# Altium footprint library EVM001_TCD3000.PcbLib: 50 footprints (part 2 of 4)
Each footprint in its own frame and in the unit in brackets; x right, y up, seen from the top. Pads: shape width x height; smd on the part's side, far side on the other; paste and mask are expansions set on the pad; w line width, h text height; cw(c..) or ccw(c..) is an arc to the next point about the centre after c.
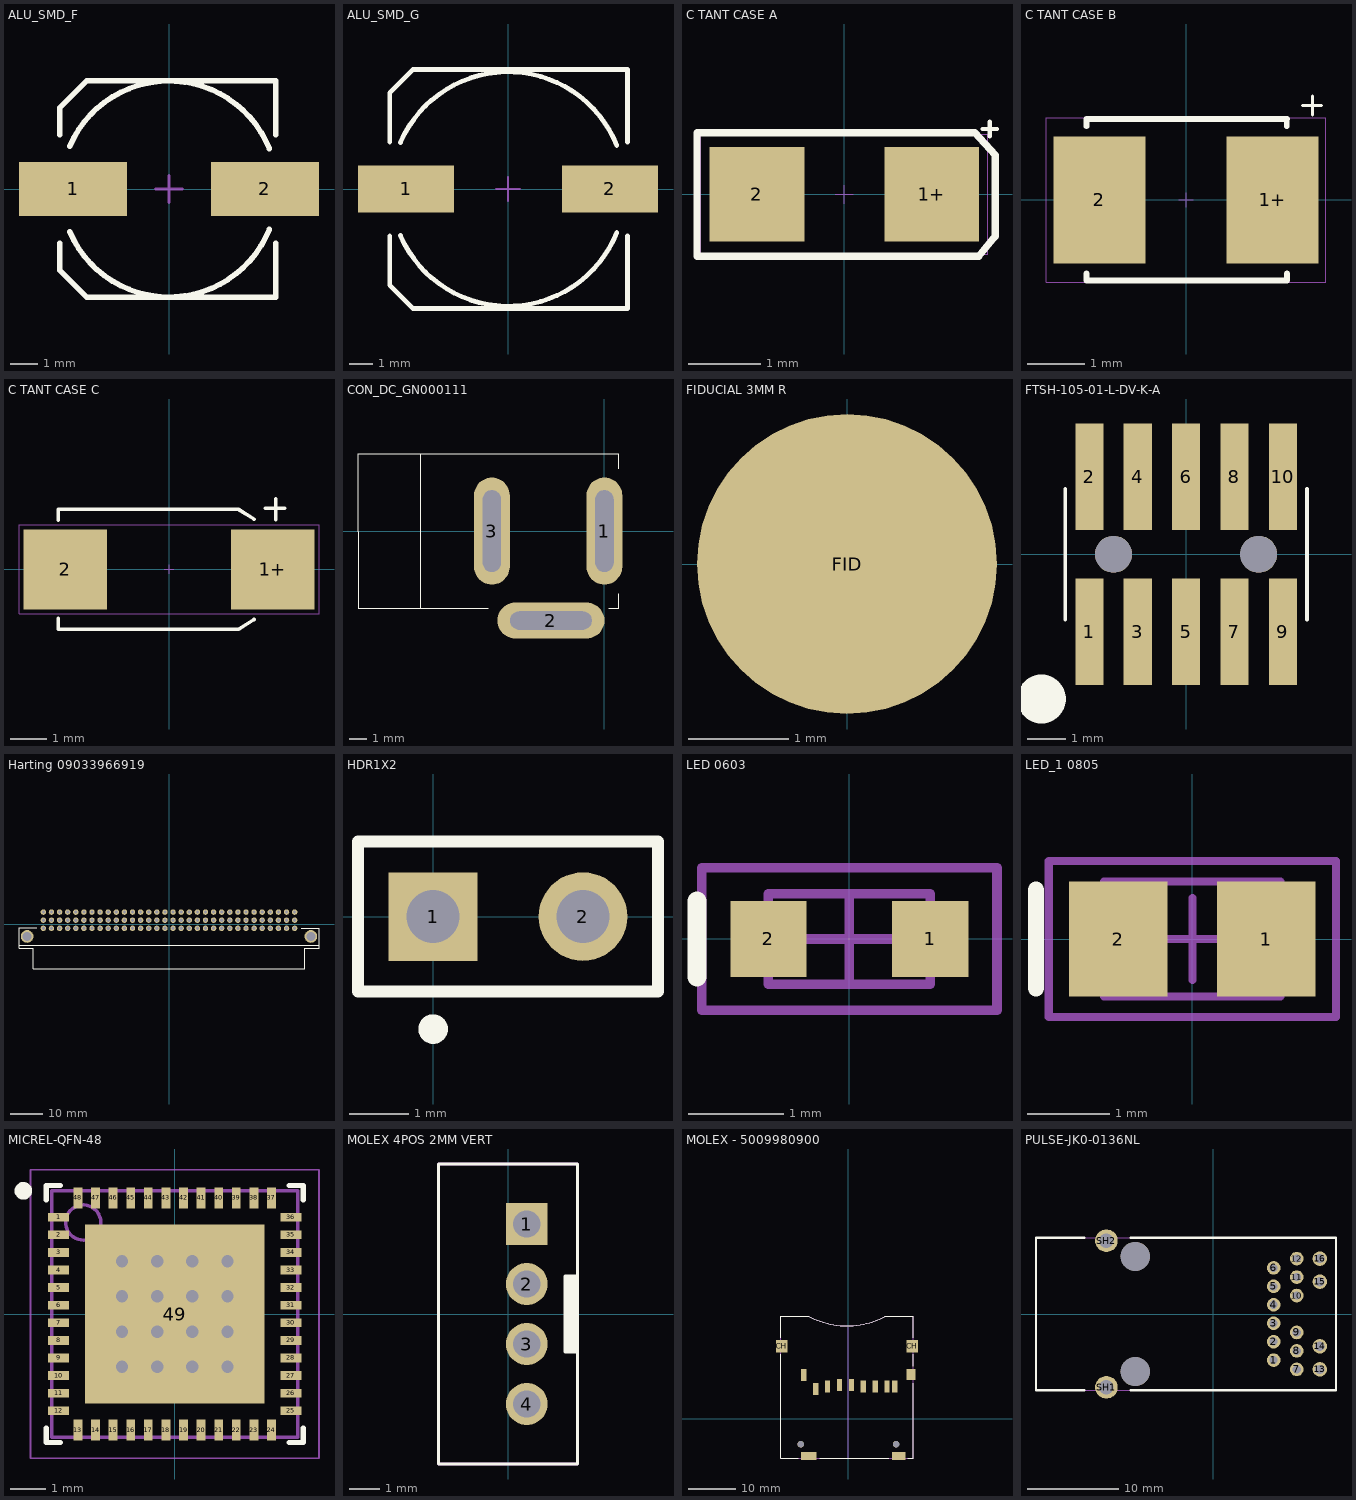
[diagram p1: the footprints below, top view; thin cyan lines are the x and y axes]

## ALU_SMD_F [mm]
pads (2):
  rect 4x2 smd: 1(-3.55,0) 2(3.55,0)
Top Overlay:
  lines w0.203: -4.05,-2 -4.05,-3 -3.05,-4 3.95,-4 3.95,-2 ; -4.05,2 -4.05,3 -3.05,4 3.95,4 3.95,2 ; -3.67,-1.59 ccw(c0,0) 3.714,-1.486 ; -3.67,1.59 cw(c0,0) 3.714,1.486
Mechanical 15:
  lines w0.1: -0.5,0 0.5,0 ; 0,-0.5 0,0.5
3D body: height 10.2, standoff 0, extent -4.95,-4.15 4.95,4.15

## ALU_SMD_G [mm]
pads (2):
  rect 4.1x2 smd: 1(-4.35,0) 2(4.35,0)
Top Overlay:
  lines w0.2: -5.05,-4.1 -4.05,-5.1 ; -5.05,4.1 -4.05,5.1
  lines w0.203: -5.05,-4.1 -5.05,-2 ; -5.05,2 -5.05,4.1 ; -4.588,-1.988 ccw(c0,0) 4.642,-1.857 ; -4.588,1.988 cw(c0,0) 4.642,1.857 ; -4.05,-5.1 5.1,-5.1 5.1,-2 ; -4.05,5.1 5.1,5.1 5.1,2
Mechanical 15:
  lines w0.1: -0.5,0 0.5,0 ; 0,-0.5 0,0.5
3D body: height 10.2, standoff 0, extent -4.95,-4.15 4.95,4.15

## C TANT CASE A [mm] "Tantalum Capacitor Case A"
height 1.6
pads (2):
  rect 1.3x1.3 smd: 1+(1.2,0) 2(-1.2,0)
Top Overlay:
  lines w0.06: 1.9,0.9 2.1,0.9 ; 2,0.8 2,1
  lines w0.1: -2.025,-0.85 -2.025,0.85 1.797,0.85 2.075,0.539 2.075,-0.573 1.85,-0.85 -2.025,-0.85
Mechanical 15:
  lines w0.015: -0.125,0 0.125,0 ; 0,-0.125 0,0.125 ; -1.975,-0.825 -1.975,0.825 1.975,0.825 1.975,-0.825 -1.975,-0.825
3D body: height 1.61, standoff 0, extent -1.595,-0.8 1.596,0.8

## C TANT CASE B [mm] "Tantalum Capacitor Case B"
height 1.9
pads (2):
  rect 1.6x2.2 smd: 1+(1.5,0) 2(-1.5,0)
Top Overlay:
  lines w0.05: 2.019,1.633 2.349,1.633 ; 2.19,1.47 2.19,1.8
  lines w0.1: -1.725,-1.275 -1.725,-1.4 1.75,-1.4 1.75,-1.275 ; -1.725,1.275 -1.725,1.4 1.75,1.4 ; 1.746,1.275 1.746,1.4
Mechanical 15:
  lines w0.015: -0.125,0 0.125,0 ; 0,-0.125 0,0.125 ; -2.425,-1.425 2.425,-1.425 2.425,1.425 -2.425,1.425 -2.425,-1.425
3D body: height 1.91, standoff 0, extent -1.746,-1.4 1.746,1.4

## C TANT CASE C [mm] "Tantalum Capacitor Case C"
height 2.6
pads (2):
  rect 2.3x2.2 smd: 1+(2.85,0) 2(-2.85,0)
Top Overlay:
  lines w0.1: -3.048,-1.348 -3.048,-1.651 1.905,-1.651 2.338,-1.38 ; -3.048,1.348 -3.048,1.651 1.905,1.651 2.338,1.38 ; 2.654,1.676 3.175,1.676 ; 2.934,1.359 2.934,1.943
Mechanical 15:
  lines w0.015: -0.125,0 0.125,0 ; 0,-0.125 0,0.125 ; -4.125,-1.225 -4.125,1.225 4.125,1.225 4.125,-1.225 -4.125,-1.225

## CON_DC_GN000111 [mil] "DC connector"
pads (3):
  oval 79x236 hole 40 slot 180 at 90 deg: 1(0,0) 3(-248,0)
  oval 236x79 hole 40 slot 180 at 0 deg: 2(-118,-197)
Top Overlay:
  lines w2: -405,-170 -405,170 -543,170 ; -255.91,-170 -543,-170 -543,-1 -543,170 ; 10,-170 32,-170 32,-137.8 ; 32,137.8 32,170 -543,170
3D body: height 433.07, standoff -137.8, extent -544.35,-199.23 0,175

## FIDUCIAL 3MM R [mm]
pads (1):
  round 3 smd paste-1.5: FID(0,0)

## FTSH-105-01-L-DV-K-A [mm] "SMD Micro Header 1.27mm Pitch"
pads (12):
  rect 0.74x2.79 smd: 1(-2.54,-2.035) 2(-2.54,2.035) 3(-1.27,-2.035) 4(-1.27,2.035) 5(0,-2.035) 6(0,2.035) 7(1.27,-2.035) 8(1.27,2.035) 9(2.54,-2.035) 10(2.54,2.035)
  round 0.97 hole 0.97 unplated: ""(-1.905,0) ""(1.905,0)
Top Overlay:
  circle w1: c-3.8,-3.8 r0.141
  lines w0.1: -3.175,-1.715 -3.175,1.715 ; 3.175,-1.715 3.175,1.715
3D body: height 6.16, standoff -0.82, extent -3.175,-2.921 3.175,2.921

## Harting 09033966919 [mm] "VME male Connecotr"
pads (98):
  round 1.7 hole 1: A1(39.37,-1.27) A2(36.83,-1.27) A3(34.29,-1.27) A4(31.75,-1.27) A5(29.21,-1.27) A6(26.67,-1.27) A7(24.13,-1.27) A8(21.59,-1.27) A9(19.05,-1.27) A10(16.51,-1.27) A11(13.97,-1.27) A12(11.43,-1.27) A13(8.89,-1.27) A14(6.35,-1.27) A15(3.81,-1.27) A16(1.27,-1.27) A17(-1.27,-1.27) A18(-3.81,-1.27) A19(-6.35,-1.27) A20(-8.89,-1.27) A21(-11.43,-1.27) A22(-13.97,-1.27) A23(-16.51,-1.27) A24(-19.05,-1.27) A25(-21.59,-1.27) A26(-24.13,-1.27) A27(-26.67,-1.27) A28(-29.21,-1.27) A29(-31.75,-1.27) A30(-34.29,-1.27) A31(-36.83,-1.27) A32(-39.37,-1.27) B1(39.37,1.27) B2(36.83,1.27) B3(34.29,1.27) B4(31.75,1.27) B5(29.21,1.27) B6(26.67,1.27) B7(24.13,1.27) B8(21.59,1.27) B9(19.05,1.27) B10(16.51,1.27) B11(13.97,1.27) B12(11.43,1.27) B13(8.89,1.27) B14(6.35,1.27) B15(3.81,1.27) B16(1.27,1.27) B17(-1.27,1.27) B18(-3.81,1.27) B19(-6.35,1.27) B20(-8.89,1.27) B21(-11.43,1.27) B22(-13.97,1.27) B23(-16.51,1.27) B24(-19.05,1.27) B25(-21.59,1.27) B26(-24.13,1.27) B27(-26.67,1.27) B28(-29.21,1.27) B29(-31.75,1.27) B30(-34.29,1.27) B31(-36.83,1.27) B32(-39.37,1.27) C1(39.37,3.81) C2(36.83,3.81) C3(34.29,3.81) C4(31.75,3.81) C5(29.21,3.81) C6(26.67,3.81) C7(24.13,3.81) C8(21.59,3.81) C9(19.05,3.81) C10(16.51,3.81) C11(13.97,3.81) C12(11.43,3.81) C13(8.89,3.81) C14(6.35,3.81) C15(3.81,3.81) C16(1.27,3.81) C17(-1.27,3.81) C18(-3.81,3.81) C19(-6.35,3.81) C20(-8.89,3.81) C21(-11.43,3.81) C22(-13.97,3.81) C23(-16.51,3.81) C24(-19.05,3.81) C25(-21.59,3.81) C26(-24.13,3.81) C27(-26.67,3.81) C28(-29.21,3.81) C29(-31.75,3.81) C30(-34.29,3.81) C31(-36.83,3.81) C32(-39.37,3.81)
  round 4 hole 2.8: ""(-44.45,-3.81) ""(44.45,-3.81)
Top Overlay:
  lines w0.1: -42.5,-13.91 -42.5,-7.51 -47,-7.51 -47,-1.11 -41.5,-1.11 ; 41.5,-1.21 47,-1.21 47,-7.51 42.5,-7.51 42.5,-13.91
  lines w0.15: -42.5,-13.91 42.5,-13.91
  lines w0.254: -47,-6.57 47,-6.57
3D body: height 9.35, standoff -3, extent -47.01,-13.97 46.99,4.05

## HDR1X2 [mm]
height 0.71
pads (2):
  rect 1.5x1.5 hole 0.9: 1(0,0)
  round 1.5 hole 0.9: 2(2.54,0)
Top Overlay:
  circle w0.25: c0.002,-1.905 r0.125
  lines w0.2: -1.27,-1.27 3.81,-1.27 3.81,1.27 -1.27,1.27 -1.27,-1.27
3D body: height 8.14, standoff -3.03, extent -0.94,-1.194 3.734,1.143

## LED 0603 [mm]
height 1
pads (2):
  rect 0.8x0.8 smd: 1(0.85,0) 2(-0.85,0)
Top Overlay:
  lines w0.2: -1.6,-0.4 -1.6,0.4
Mechanical 13:
  lines w0.1: -0.85,-0.475 -0.85,0.475 0.85,0.475 0.85,-0.475 -0.85,-0.475
Mechanical 15:
  lines w0.1: -0.475,0 0.475,0 ; 0,-0.475 0,0.475 ; -1.55,-0.75 -1.55,0.75 1.55,0.75 1.55,-0.75 -1.55,-0.75
3D body: height 0.68, standoff 0, extent -0.825,-0.344 0.825,0.381

## LED_1 0805 [mm] "LED SMD"
pads (2):
  rect 1.2x1.4 smd: 1(0.9,0) 2(-0.9,0)
Top Overlay:
  lines w0.2: -1.905,-0.6 -1.905,0.6
Mechanical 13:
  lines w0.1: -1.075,-0.7 1.075,-0.7 1.075,0.7 -1.075,0.7 -1.075,-0.7
Mechanical 15:
  lines w0.1: -0.5,0 0.5,0 ; 0,-0.5 0,0.5 ; -1.75,-0.95 1.75,-0.95 1.75,0.95 -1.75,0.95 -1.75,-0.95
3D body: height 0.68, standoff 0, extent -0.825,-0.344 0.825,0.381

## MICREL-QFN-48 [mm]
height 0.9
pads (49):
  rect 0.6x0.25 smd: 1(-3.3,2.75) 2(-3.3,2.25) 3(-3.3,1.75) 4(-3.3,1.25) 5(-3.3,0.75) 6(-3.3,0.25) 7(-3.3,-0.25) 8(-3.3,-0.75) 9(-3.3,-1.25) 10(-3.3,-1.75) 11(-3.3,-2.25) 12(-3.3,-2.75) 25(3.3,-2.75) 26(3.3,-2.25) 27(3.3,-1.75) 28(3.3,-1.25) 29(3.3,-0.75) 30(3.3,-0.25) 31(3.3,0.25) 32(3.3,0.75) 33(3.3,1.25) 34(3.3,1.75) 35(3.3,2.25) 36(3.3,2.75)
  rect 0.25x0.6 smd: 13(-2.75,-3.3) 14(-2.25,-3.3) 15(-1.75,-3.3) 16(-1.25,-3.3) 17(-0.75,-3.3) 18(-0.25,-3.3) 19(0.25,-3.3) 20(0.75,-3.3) 21(1.25,-3.3) 22(1.75,-3.3) 23(2.25,-3.3) 24(2.75,-3.3) 37(2.75,3.3) 38(2.25,3.3) 39(1.75,3.3) 40(1.25,3.3) 41(0.75,3.3) 42(0.25,3.3) 43(-0.25,3.3) 44(-0.75,3.3) 45(-1.25,3.3) 46(-1.75,3.3) 47(-2.25,3.3) 48(-2.75,3.3)
  rect 5.1x5.1 smd paste-2.55 mask-2.55: 49(0,0)
via 1.5,1.5 diameter 0.5 hole 0.35
via 0.5,1.5 diameter 0.5 hole 0.35
via -0.5,1.5 diameter 0.5 hole 0.35
via 1.5,-1.5 diameter 0.5 hole 0.35
via 0.5,-1.5 diameter 0.5 hole 0.35
via -0.5,-1.5 diameter 0.5 hole 0.35
via -1.5,1.5 diameter 0.5 hole 0.35
via -1.5,-1.5 diameter 0.5 hole 0.35
via -1.5,0.5 diameter 0.5 hole 0.35
via -1.5,-0.5 diameter 0.5 hole 0.35
via 1.5,0.5 diameter 0.5 hole 0.35
via -0.5,0.5 diameter 0.5 hole 0.35
via -0.5,-0.5 diameter 0.5 hole 0.35
via 1.5,-0.5 diameter 0.5 hole 0.35
via 0.5,0.5 diameter 0.5 hole 0.35
via 0.5,-0.5 diameter 0.5 hole 0.35
Top Overlay:
  circle w0.25: c-4.3,3.5 r0.125
  lines w0.15: -3.65,-3.25 -3.65,-3.65 -3.25,-3.65 ; -3.65,3.25 -3.65,3.65 -3.25,3.65 ; 3.25,-3.65 3.65,-3.65 3.65,-3.25 ; 3.25,3.65 3.65,3.65 3.65,3.25
Top Paste:
  rectangle: -1,0.1 -0.1,1
  rectangle: 0.1,0.1 1,1
  rectangle: -1,-1 -0.1,-0.1
  rectangle: 0.1,-1 1,-0.1
  rectangle: -1,-2.1 -0.1,-1.2
  rectangle: 0.1,-2.1 1,-1.2
  rectangle: 1.2,-2.1 2.1,-1.2
  rectangle: 1.2,-1 2.1,-0.1
  rectangle: 1.2,0.1 2.1,1
  rectangle: 1.2,1.2 2.1,2.1
  rectangle: 0.1,1.2 1,2.1
  rectangle: -1,1.2 -0.1,2.1
  rectangle: -2.1,1.2 -1.2,2.1
  rectangle: -2.1,0.1 -1.2,1
  rectangle: -2.1,-1 -1.2,-0.1
  rectangle: -2.1,-2.1 -1.2,-1.2
Top Solder:
  rectangle: -2.1,-2.1 -1.2,-1.2
  rectangle: -2.1,-1 -1.2,-0.1
  rectangle: -2.1,0.1 -1.2,1
  rectangle: -2.1,1.2 -1.2,2.1
  rectangle: -1,1.2 -0.1,2.1
  rectangle: 0.1,1.2 1,2.1
  rectangle: 1.2,1.2 2.1,2.1
  rectangle: 1.2,0.1 2.1,1
  rectangle: 1.2,-1 2.1,-0.1
  rectangle: 1.2,-2.1 2.1,-1.2
  rectangle: 0.1,-2.1 1,-1.2
  rectangle: -1,-2.1 -0.1,-1.2
  rectangle: 0.1,-1 1,-0.1
  rectangle: -1,-1 -0.1,-0.1
  rectangle: 0.1,0.1 1,1
  rectangle: -1,0.1 -0.1,1
Mechanical 13:
  circle w0.1: c-2.6,2.6 r0.5
  lines w0.1: -3.5,-3.5 3.5,-3.5 3.5,3.5 -3.5,3.5 -3.5,-3.5
Mechanical 15:
  lines w0.05: -4.1,-4.1 4.1,-4.1 4.1,4.1 -4.1,4.1 -4.1,-4.1
  lines w0.1: -0.5,0 0.5,0 ; 0,-0.5 0,0.5
3D body: height 0.9, standoff 0, extent -3.5,-3.5 3.5,3.5

## MOLEX 4POS 2MM VERT [mm] "CONN HEADER 4POS 2MM VERT T/H"
pads (4):
  rect 1.4x1.4 hole 0.9: 1(0.625,3)
  round 1.4 hole 0.9: 2(0.625,1) 3(0.625,-1) 4(0.625,-3)
Top Overlay:
  rectangle: 1.905,-1.27 2.325,1.27
  lines w0.1: 2.325,-1.27 1.905,-1.27 1.905,1.27 2.325,1.27 ; -2.325,-5 2.325,-5 2.325,5 -2.325,5 -2.325,-5
Mechanical 13:
  lines w0.1: -2.325,-5 -2.325,5 2.325,5 2.325,-5 -2.325,-5
3D body: height 6.53, standoff -2.93, extent -2.364,-5 2.286,5

## MOLEX - 5009980900 [mm] "2.50mm (.098\") Pitch SD Memory Card Connector, Shielded, Top Mount, Push-Push Ejector"
height 3.1
pads (16):
  rect 1.1x2.5 smd: 1(-6.875,6.25) 2(-4.375,6.75) 3(-1.875,7.05) 4(0.625,7.05) 5(3.125,6.75) 6(5.625,6.75) 7(8.125,6.75) 8(9.75,6.75) 9(-9.375,9.15)
  rect 2.5x2.6 smd: CH(-14,15.25) CH(13.4,15.25)
  rect 2.8x1.7 smd: COMM(10.55,-7.85)
  rect 3.3x1.7 smd: DTSW(-8.35,-7.85)
  rect 1.95x2.3 smd: PSW(13.125,9.25)
  round 1.36 hole 1.36: ""(-10,-5.35) ""(10,-5.35)
Top Overlay:
  lines w0.1: -14.25,13.5 -14.25,-8.25 -10.5,-8.25 ; -14.25,17 -14.25,21.55 -8.35,21.55 ccw(c-0.294,36.511) 7.702,21.518 ; -6,-8.25 8.5,-8.25 ; 7.65,21.55 13.65,21.55 13.65,17 ; 12.5,-8.25 13.65,-8.25 13.65,7.5 ; 13.65,11 13.65,13.5
Mechanical 13:
  lines w0.1: 0,-8.25 0,19.5 ; 7.65,21.55 13.65,21.55 13.65,-8.25 -14.25,-8.25 -14.25,21.55 -8.35,21.55 ccw(c-0.294,36.511) 7.702,21.518
3D body: height 3.15, standoff -0.45, extent -14.75,-8.5 14.15,21.55

## PULSE-JK0-0136NL [mil]
pads (20):
  round 59.06 hole 35: 1(262.5,-200) 2(262.5,-120) 3(262.5,-40) 4(262.5,40) 5(262.5,120) 6(262.5,200) 7(362.5,-240) 8(362.5,-160) 9(362.5,-80) 10(362.5,80) 11(362.5,160) 12(362.5,240)
  round 62.99 hole 40: 13(462.5,-240) 14(462.5,-140) 15(462.5,140) 16(462.5,240)
  round 98.43 hole 62: SH1(-462.5,-317.5) SH2(-462.5,317.5)
  round 126 hole 126 unplated mask+0: ""(-337.5,-250) ""(-337.5,250)
Top Overlay:
  lines w10: -557.5,-330 -767.5,-330 -767.5,330 -557.5,330 ; -357.5,-330 532.5,-330 532.5,330 -357.5,330
Mechanical 10:
  lines w5: -767.5,-330 532.5,-330 532.5,330 -767.5,330 -767.5,-330
3D body: height 590, standoff 0, extent -767.5,-330 532.5,330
